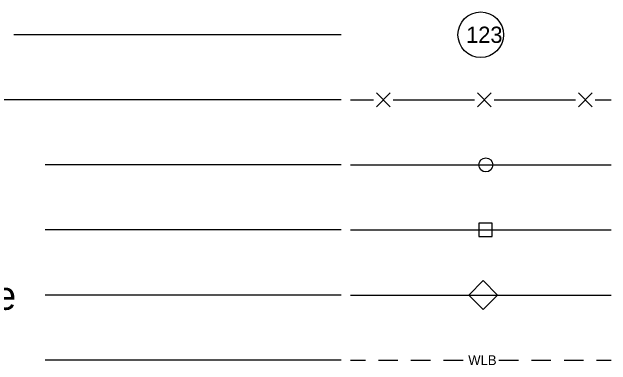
# Model space of a CAD drawing. Extents: x 2040834 to 2047174, y 618431 to 621625.
# Drawn here: x 2045324.9 to 2045541.4, y 621168.2 to 621295.9 of the extents above; entities that cross this region are included whole.
import ezdxf

# ---------------------------------------------------------------- set-up
doc = ezdxf.new("R2010")
doc.units = 0
doc.layers.add('Default', color=7, linetype='Continuous')

msp = doc.modelspace()

# ---------------------------------------------------------------- linework, layer by layer
at = {"layer": 'Default'}
for p, q in [((2045443.84, 621287.64), (2045325.56, 621287.64)), ((2045456.64, 621261.62), (2045461.58, 621266.57)), ((2045461.58, 621261.62), (2045456.64, 621266.57)), ((2045493.13, 621261.62), (2045498.07, 621266.57)), ((2045498.07, 621261.62), (2045493.13, 621266.57)), ((2045529.62, 621261.62), (2045534.56, 621266.57)), ((2045534.56, 621261.62), (2045529.62, 621266.57)), ((2045443.84, 621264.1), (2045273.03, 621264.1)), ((2045447.22, 621264.1), (2045455.58, 621264.1)), ((2045462.64, 621264.1), (2045477.36, 621264.1)), ((2045477.36, 621264.1), (2045492.07, 621264.1)), ((2045499.13, 621264.1), (2045513.85, 621264.1)), ((2045513.85, 621264.1), (2045528.56, 621264.1)), ((2045535.62, 621264.1), (2045541.39, 621264.1)), ((2045443.84, 621240.55), (2045336.91, 621240.55)), ((2045447.22, 621240.55), (2045541.39, 621240.55)), ((2045447.22, 621240.55), (2045541.39, 621240.55)), ((2045443.84, 621217.01), (2045336.91, 621217.01)), ((2045447.22, 621217.01), (2045541.39, 621217.01)), ((2045447.22, 621217.01), (2045541.39, 621217.01)), ((2045443.84, 621193.47), (2045336.91, 621193.47)), ((2045447.22, 621193.47), (2045541.39, 621193.47)), ((2045447.22, 621193.47), (2045541.39, 621193.47)), ((2045443.84, 621169.93), (2045336.91, 621169.93)), ((2045447.22, 621169.93), (2045452.61, 621169.93)), ((2045457.32, 621169.93), (2045464.38, 621169.93)), ((2045469.09, 621169.93), (2045476.15, 621169.93)), ((2045480.86, 621169.93), (2045487.92, 621169.93)), ((2045500.87, 621169.93), (2045507.93, 621169.93)), ((2045512.64, 621169.93), (2045519.7, 621169.93)), ((2045524.41, 621169.93), (2045531.47, 621169.93)), ((2045536.18, 621169.93), (2045541.39, 621169.93))]:
    msp.add_line(p, q, dxfattribs=at)
for points in [[(2045493.57, 621214.6), (2045498.4, 621214.6), (2045498.4, 621219.42), (2045493.57, 621219.42)], [(2045495.13, 621188.29), (2045500.31, 621193.47), (2045495.13, 621198.71), (2045489.95, 621193.47)]]:
    msp.add_lwpolyline(points, close=True, dxfattribs=at)
for centre, radius in [((2045494.31, 621287.64), 8.24), ((2045496.16, 621240.55), 2.53)]:
    msp.add_circle(centre, radius, dxfattribs=at)

# ---------------------------------------------------------------- texts
for s, height, p in [('123', 5.885, (2045489.04, 621284.69)), ('Proposed Barbed Wire Fence', 10.2996, (2045145, 621188.13)), ('WLB', 3.531, (2045489.8, 621168.16))]:
    msp.add_text(s, height=height, dxfattribs=at).set_placement(p)

doc.saveas('drawing.dxf')
